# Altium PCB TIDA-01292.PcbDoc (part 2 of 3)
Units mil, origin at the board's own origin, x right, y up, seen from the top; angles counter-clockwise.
Board outline 6102.36 x 3543.31 mil, 2 copper layers (Top Layer, Bottom Layer), stack 64.8 mil thick; 118 components, 43 nets, 376 pads, 3910 vias.
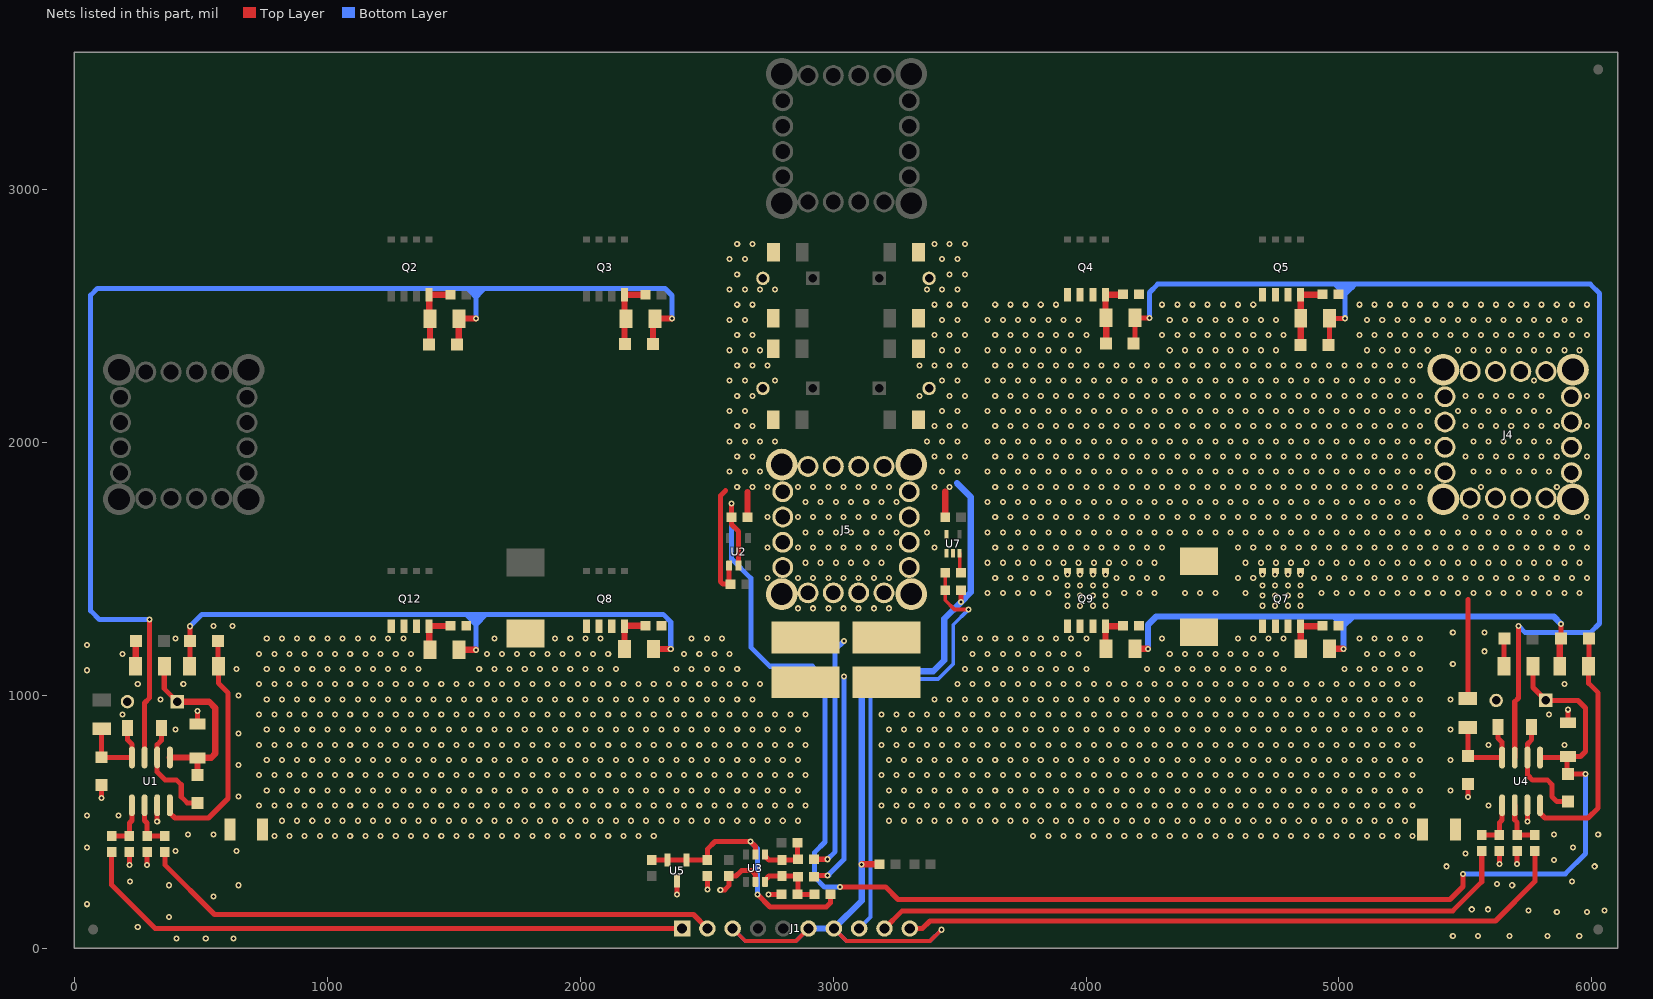
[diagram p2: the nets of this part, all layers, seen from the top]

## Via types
v1: diameter 24, hole 12, Top Layer to Bottom Layer, 3910 vias

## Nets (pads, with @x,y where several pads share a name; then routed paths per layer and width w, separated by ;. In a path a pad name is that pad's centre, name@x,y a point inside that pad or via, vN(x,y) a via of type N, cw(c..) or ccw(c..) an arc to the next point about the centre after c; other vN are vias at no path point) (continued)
"COMMON B": D11.1 J4.1 pad.1@5412.97,1776.37 pad.1@5412.97,2288.18 pad.1@5924.78,1776.37 pad.1@5924.78,2288.18 Q4.1 Q4.2 Q4.3 Q5.1 Q5.2 Q5.3 Q7.5 Q7.6 Q7.7 Q7.8 Q9.5 Q9.6 Q9.7 Q9.8 R27.2 R34.1 R35.1 | length 392.4
  Top Layer w20: R27.2@5510,987.6 5510,1380
  other v1: 3927,1355 3977,1355 4027,1355 4077,1355 4698,1355 4748,1355 4798,1355 4848,1355 3927,1395 3977,1395 4027,1395 4077,1395 4698,1395 4748,1395 4798,1395 4848,1395 3611.15,1405 3671.15,1405 3731.15,1405 3791.15,1405 3851.15,1405 4151.15,1405 4211.15,1405 4271.15,1405 4391.15,1405 4451.15,1405 4511.15,1405 4631.15,1405 4931.15,1405 4991.15,1405 5051.15,1405 5111.15,1405 5171.15,1405 5231.15,1405 5291.15,1405 5351.15,1405 5411.15,1405 5471.15,1405 5531.15,1405 5591.15,1405 5651.15,1405 5711.15,1405 5771.15,1405 5831.15,1405 5891.15,1405 5951.15,1405 3927,1435 3977,1435 4027,1435 4077,1435 4698,1435 4748,1435 4798,1435 4848,1435 3641.15,1465 3701.15,1465 3761.15,1465 3821.15,1465 3881.15,1465 4121.15,1465 4181.15,1465 4241.15,1465 4301.15,1465 4601.15,1465 4661.15,1465 4901.15,1465 4961.15,1465 5021.15,1465 5081.15,1465 5141.15,1465 5201.15,1465 5261.15,1465 5321.15,1465 5381.15,1465 5441.15,1465 5501.15,1465 5561.15,1465 5621.15,1465 5681.15,1465 5741.15,1465 5801.15,1465 5861.15,1465 5921.15,1465 5981.15,1465 3927,1479 3977,1479 4027,1479 4077,1479 4698,1479 4748,1479 4798,1479 4848,1479 3611.15,1525 3671.15,1525 3731.15,1525 3791.15,1525 3851.15,1525 3911.15,1525 3971.15,1525 4031.15,1525 4091.15,1525 4151.15,1525 4211.15,1525 4271.15,1525 4631.15,1525 4691.15,1525 4751.15,1525 4811.15,1525 4871.15,1525 4931.15,1525 4991.15,1525 5051.15,1525 5111.15,1525 5171.15,1525 5231.15,1525 5291.15,1525 5351.15,1525 5411.15,1525 5471.15,1525 5531.15,1525 5591.15,1525 5651.15,1525 5711.15,1525 5771.15,1525 5831.15,1525 5891.15,1525 5951.15,1525 3641.15,1585 3701.15,1585 3761.15,1585 3821.15,1585 3881.15,1585 3941.15,1585 4001.15,1585 4061.15,1585 4121.15,1585 4181.15,1585 4241.15,1585 4301.15,1585 4601.15,1585 4661.15,1585 4721.15,1585 4781.15,1585 4841.15,1585 4901.15,1585 4961.15,1585 5021.15,1585 5081.15,1585 5141.15,1585 5201.15,1585 5261.15,1585 5321.15,1585 5381.15,1585 5441.15,1585 5501.15,1585 5561.15,1585 5621.15,1585 5681.15,1585 5741.15,1585 5801.15,1585 5861.15,1585 5921.15,1585 5981.15,1585 3611.15,1645 3671.15,1645 3731.15,1645 3791.15,1645 3851.15,1645 3911.15,1645 3971.15,1645 4031.15,1645 4091.15,1645 4151.15,1645 4211.15,1645 4271.15,1645 4331.15,1645 4391.15,1645 4451.15,1645 4511.15,1645 4571.15,1645 4631.15,1645 4691.15,1645 4751.15,1645 4811.15,1645 4871.15,1645 4931.15,1645 4991.15,1645 5051.15,1645 5111.15,1645 5171.15,1645 5231.15,1645 5291.15,1645 5351.15,1645 5411.15,1645 5471.15,1645 5531.15,1645 5591.15,1645 5651.15,1645 5711.15,1645 5771.15,1645 5831.15,1645 5891.15,1645 5951.15,1645 3641.15,1705 3701.15,1705 3761.15,1705 3821.15,1705 3881.15,1705 3941.15,1705 4001.15,1705 4061.15,1705 4121.15,1705 4181.15,1705 4241.15,1705 4301.15,1705 4361.15,1705 4421.15,1705 4481.15,1705 4541.15,1705 4601.15,1705 4661.15,1705 4721.15,1705 4781.15,1705 4841.15,1705 4901.15,1705 4961.15,1705 5021.15,1705 5081.15,1705 5141.15,1705 5201.15,1705 5261.15,1705 5321.15,1705 5501.15,1705 5561.15,1705 5621.15,1705 5681.15,1705 5741.15,1705 5801.15,1705 5861.15,1705 5981.15,1705 3611.15,1765 3671.15,1765 3731.15,1765 3791.15,1765 3851.15,1765 3911.15,1765 3971.15,1765 4031.15,1765 4091.15,1765 4151.15,1765 4211.15,1765 4271.15,1765 4331.15,1765 4391.15,1765 4451.15,1765 4511.15,1765 4571.15,1765 4631.15,1765 4691.15,1765 4751.15,1765 4811.15,1765 4871.15,1765 4931.15,1765 4991.15,1765 5051.15,1765 5111.15,1765 5171.15,1765 5231.15,1765 5291.15,1765 3641.15,1825 3701.15,1825 3761.15,1825 3821.15,1825 3881.15,1825 3941.15,1825 4001.15,1825 4061.15,1825 4121.15,1825 4181.15,1825 4241.15,1825 4301.15,1825 4361.15,1825 4421.15,1825 4481.15,1825 4541.15,1825 4601.15,1825 4661.15,1825 4721.15,1825 4781.15,1825 4841.15,1825 4901.15,1825 4961.15,1825 5021.15,1825 5081.15,1825 5141.15,1825 5201.15,1825 5261.15,1825 5321.15,1825 5561.15,1825 5861.15,1825 3611.15,1885 3671.15,1885 3731.15,1885 3791.15,1885 3851.15,1885 3911.15,1885 3971.15,1885 4031.15,1885 4091.15,1885 4151.15,1885 4211.15,1885 4271.15,1885 4331.15,1885 4391.15,1885 4451.15,1885 4511.15,1885 4571.15,1885 4631.15,1885 4691.15,1885 4751.15,1885 4811.15,1885 4871.15,1885 4931.15,1885 4991.15,1885 5051.15,1885 5111.15,1885 5171.15,1885 5231.15,1885 5291.15,1885 5351.15,1885 5531.15,1885 5591.15,1885 5651.15,1885 5711.15,1885 5771.15,1885 5831.15,1885 3641.15,1945 3701.15,1945 3761.15,1945 3821.15,1945 3881.15,1945 3941.15,1945 4001.15,1945 4061.15,1945 4121.15,1945 4181.15,1945 4241.15,1945 4301.15,1945 4361.15,1945 4421.15,1945 4481.15,1945 4541.15,1945 4601.15,1945 4661.15,1945 4721.15,1945 4781.15,1945 4841.15,1945 4901.15,1945 4961.15,1945 5021.15,1945 5081.15,1945 5141.15,1945 5201.15,1945 5261.15,1945 5321.15,1945 5501.15,1945 5561.15,1945 5621.15,1945 5681.15,1945 5741.15,1945 5801.15,1945 5861.15,1945 5981.15,1945 3611.15,2005 3671.15,2005 3731.15,2005 3791.15,2005 3851.15,2005 3911.15,2005 3971.15,2005 4031.15,2005 4091.15,2005 4151.15,2005 4211.15,2005 4271.15,2005 4331.15,2005 4391.15,2005 4451.15,2005 4511.15,2005 4571.15,2005 4631.15,2005 4691.15,2005 4751.15,2005 4811.15,2005 4871.15,2005 4931.15,2005 4991.15,2005 5051.15,2005 5111.15,2005 5171.15,2005 5231.15,2005 5291.15,2005 5351.15,2005 5531.15,2005 5591.15,2005 5651.15,2005 5711.15,2005 5771.15,2005 5831.15,2005 3641.15,2065 3701.15,2065 3761.15,2065 3821.15,2065 3881.15,2065 3941.15,2065 4001.15,2065 4061.15,2065 4121.15,2065 4181.15,2065 4241.15,2065 4301.15,2065 4361.15,2065 4421.15,2065 4481.15,2065 4541.15,2065 4601.15,2065 4661.15,2065 4721.15,2065 4781.15,2065 4841.15,2065 4901.15,2065 4961.15,2065 5021.15,2065 5081.15,2065 5141.15,2065 5201.15,2065 5261.15,2065 5321.15,2065 5501.15,2065 5561.15,2065 5621.15,2065 5681.15,2065 5741.15,2065 5801.15,2065 5861.15,2065 5981.15,2065 3611.15,2125 3671.15,2125 3731.15,2125 3791.15,2125 3851.15,2125 3911.15,2125 3971.15,2125 4031.15,2125 4091.15,2125 4151.15,2125 4211.15,2125 4271.15,2125 4331.15,2125 4391.15,2125 4451.15,2125 4511.15,2125 4571.15,2125 4631.15,2125 4691.15,2125 4751.15,2125 4811.15,2125 4871.15,2125 4931.15,2125 4991.15,2125 5051.15,2125 5111.15,2125 5171.15,2125 5231.15,2125 5291.15,2125 5351.15,2125 5471.15,2125 5531.15,2125 5591.15,2125 5651.15,2125 5711.15,2125 5771.15,2125 5831.15,2125 3641.15,2185 3701.15,2185 3761.15,2185 3821.15,2185 3881.15,2185 3941.15,2185 4001.15,2185 4061.15,2185 4121.15,2185 4181.15,2185 4241.15,2185 4301.15,2185 4361.15,2185 4421.15,2185 4481.15,2185 4541.15,2185 4601.15,2185 4661.15,2185 4721.15,2185 4781.15,2185 4841.15,2185 4901.15,2185 4961.15,2185 5021.15,2185 5081.15,2185 5141.15,2185 5201.15,2185 5261.15,2185 5321.15,2185 5501.15,2185 5561.15,2185 5621.15,2185 5681.15,2185 5741.15,2185 5801.15,2185 5981.15,2185 3611.15,2245 3671.15,2245 3731.15,2245 3791.15,2245 3851.15,2245 3911.15,2245 3971.15,2245 4031.15,2245 4091.15,2245 4151.15,2245 4211.15,2245 4271.15,2245 4331.15,2245 4391.15,2245 4451.15,2245 4511.15,2245 4571.15,2245 4631.15,2245 4691.15,2245 4751.15,2245 4811.15,2245 4871.15,2245 4931.15,2245 4991.15,2245 5051.15,2245 5111.15,2245 5171.15,2245 5231.15,2245 5291.15,2245 5771.15,2245 3641.15,2305 3701.15,2305 3761.15,2305 3821.15,2305 3881.15,2305 3941.15,2305 4001.15,2305 4061.15,2305 4121.15,2305 4181.15,2305 4241.15,2305 4301.15,2305 4361.15,2305 4421.15,2305 4481.15,2305 4541.15,2305 4601.15,2305 4661.15,2305 4721.15,2305 4781.15,2305 4841.15,2305 4901.15,2305 4961.15,2305 5021.15,2305 5081.15,2305 5141.15,2305 5201.15,2305 5261.15,2305 5321.15,2305 3611.15,2365 3671.15,2365 3731.15,2365 3791.15,2365 3851.15,2365 3911.15,2365 3971.15,2365 4331.15,2365 4391.15,2365 4451.15,2365 4511.15,2365 4571.15,2365 4631.15,2365 4691.15,2365 4751.15,2365 5111.15,2365 5171.15,2365 5231.15,2365 5291.15,2365 5351.15,2365 5471.15,2365 5531.15,2365 5591.15,2365 5651.15,2365 5711.15,2365 5771.15,2365 5831.15,2365 5891.15,2365 5951.15,2365 3641.15,2425 3701.15,2425 3761.15,2425 3821.15,2425 3881.15,2425 3941.15,2425 4001.15,2425 4301.15,2425 4361.15,2425 4421.15,2425 4481.15,2425 4541.15,2425 4601.15,2425 4661.15,2425 4721.15,2425 4781.15,2425 5081.15,2425 5141.15,2425 5201.15,2425 5261.15,2425 5321.15,2425 5381.15,2425 5441.15,2425 5501.15,2425 5561.15,2425 5621.15,2425 5681.15,2425 5741.15,2425 5801.15,2425 5861.15,2425 5921.15,2425 5981.15,2425 3611.15,2485 3671.15,2485 3731.15,2485 3791.15,2485 3851.15,2485 3911.15,2485 3971.15,2485 4331.15,2485 4391.15,2485 4451.15,2485 4511.15,2485 4571.15,2485 4631.15,2485 4691.15,2485 4751.15,2485 5111.15,2485 5171.15,2485 5231.15,2485 5291.15,2485 5351.15,2485 5411.15,2485 5471.15,2485 5531.15,2485 5591.15,2485 5651.15,2485 5711.15,2485 5771.15,2485 5831.15,2485 5891.15,2485 5951.15,2485 3641.15,2545 3701.15,2545 3761.15,2545 3821.15,2545 3881.15,2545 4301.15,2545 4361.15,2545 4421.15,2545 4481.15,2545 4541.15,2545 4601.15,2545 4661.15,2545 5081.15,2545 5141.15,2545 5201.15,2545 5261.15,2545 5321.15,2545 5381.15,2545 5441.15,2545 5501.15,2545 5561.15,2545 5621.15,2545 5681.15,2545 5741.15,2545 5801.15,2545 5861.15,2545 5921.15,2545 5981.15,2545
GHIA: D3.1 D4.1 R7.1 R8.1 U1.3 | length 5020
  Top Layer w20: U1.3@278.15,755.34 278.15,970.85 298.15,990.85 v1(298.15,1300.85)
  Top Layer w25: D3.1@1513.5,2388.4 1520.47,2395.37 R7.1@1520.47,2490.26 v1(1588.39,2490.26) ; D4.1@2288.5,2389.3 R8.1@2288.5,2483.29 ; R8.1@2295.47,2490.26 v1(2363.39,2490.26)
  Bottom Layer w20: v1(298.15,1300.85) 99.15,1300.85 65,1335 65,2582.43 92.4,2609.82 1554.24,2609.82 ; v1(1588.39,2490.26) 1588.39,2575.68 ; 1622.56,2609.85 1609.46,2596.75 ; v1(2363.39,2490.26) 2363.39,2581.61 2335.18,2609.82 1636.36,2609.82 1554.24,2609.82 ; 1554.24,2609.82 1567.31,2596.75 ; 1567.31,2596.75 1588.39,2575.68 ; 1567.31,2596.75 1609.46,2596.75 ; 1588.39,2575.68 1609.46,2596.75
GHIB: D5.1 D6.1 R10.1 R11.1 U4.3 | length 4715.2
  Top Layer w20: D5.1@4188.42,2391.09 4193.66,2396.33 R10.1@4193.66,2492.73 v1(4250.84,2492.73) ; D6.1@4958.42,2386.09 4963.08,2390.75 R11.1@4963.08,2491.42 v1(5024.33,2491.42) ; U4.3@5695,755 5695,975.51 5710,990.51 v1@5710,1273.28
  Bottom Layer w20: v1(4250.84,2492.73) 4250.84,2593.49 4283.61,2626.26 4984.67,2626.26 ; 4999.45,2611.49 5049.2,2611.49 5063.98,2626.26 ; v1(5024.33,2491.42) 5024.33,2586.61 ; 5024.33,2611.49 5024.33,2586.61 ; v1(5710,1275) 5735,1250 5995,1250 6030,1285 6030,2590 5993.74,2626.26 5063.98,2626.26 ; 4984.67,2626.26 5024.33,2586.61 ; 4984.67,2626.26 5063.98,2626.26 ; 5024.33,2586.61 5063.98,2626.26
GLIA: D15.1 R16.1 U1.8 | length 940
  Top Layer w20: U1.8@378.15,566.36 378.15,535.85 398.15,515.85 530.85,515.85 608.15,593.15 608.15,1010.85 570.24,1048.76 R16.1@570.24,1115.6 568.27,1117.57 D15.1@568.27,1215.85
GLIB: D12.1 R22.1 U4.8 | length 966.8
  Top Layer w20: U4.8@5795,566.02 5795,535.51 5815,515.51 5985,515.51 6025,555.51 6025,1010.51 5987.09,1048.43 R22.1@5987.09,1115.26 5987.84,1116.01 D12.1@5987.84,1220.92
GND: C1.2 C2.2 C3.2 C5.2 C6.2 C7.2 C8.2 C11.2 C12.2 C13.2 C14.2 C15.2 C18.2 C19.2 C20.2 C21.2 CB1.2 CB2.2 CB3.2 CB4.2 CB5.2 CB6.2 CB7.2 CB8.2 CB9.2 CB10.2 CB11.2 CB12.2 D9.2 D18.2 J1.3 J1.6 J1.7 J5.1 pad.1@2797.2,1401.03 pad.1@2797.2,1912.84 pad.1@3309.01,1401.03 pad.1@3309.01,1912.84 R2.1 R3.1 R4.1 R15.1 R18.2 U1.7 U2.1 U3.2 U4.7 U5.3 U7.1 U7.2 U7.5 | length 6646.6
  Top Layer w15: J1.3@2603.15,79 2653.15,29 2853.15,29 J1.6@2903.15,79 ; J1.7@3003.15,79 3053.15,29 3383.15,29 v1(3428.15,74)
  Top Layer w20: v1(108.15,594.24) D9.2@108.15,645.73 ; v1(218.15,329.35) C1.2@218.15,380.85 ; v1(288.15,329.35) C2.2@288.15,380.85 ; v1(328.15,502.31) U1.7@328.15,566.36 ; C11.2@487.64,887.78 v1(487.64,939.28) ; v1(2383.15,214.16) U5.3@2383.15,266.4 ; C12.2@2497.09,280.18 C12.2@2503.15,286.24 v1(2503.15,234) ; v1(2554.15,232) 2572,232 2588.15,248.15 C15.2@2588.15,286.24 2616.65,286.24 2638.15,307.74 2678.15,307.74 2693.15,292.74 U3.2@2693.15,263.61 ; 2575,1810 2555,1790 2555,1450 2564.15,1440.85 C8.2@2595.16,1440.85 2589.25,1446.76 U2.1@2589.25,1513.79 ; v1(2744.41,214) R18.2@2796.65,214 ; R2.1@2874.57,1210.85 2849.57,1235.85 2843.15,1229.43 R2.1@2891.73,1180.85 ; R4.1@2924.65,352.74 v1(2978.15,352.74) ; v1(3506.5,1370) C19.2@3506.5,1415.78 ; v1(5510,598.9) D18.2@5510,650.39 ; v1(5634.61,334.02) C3.2@5634.61,385.51 ; v1(5704.61,334.02) C5.2@5704.61,385.51 ; v1(5745,501.97) U4.7@5745,566.02 ; C14.2@5905.36,892.44 v1(5905.36,943.94)
  Top Layer w25: C7.2@2661.5,1705 2661.5,1803.5 ; v1(3113.15,332.74) R15.1@3183.15,332.74 ; C18.2@3443.5,1705 3443.5,1806.5
  Bottom Layer w15: J1.3@2603.15,79 2653.15,29 2853.15,29 J1.6@2903.15,79 ; J1.7@3003.15,79 3053.15,29 3383.15,29 v1(3428.15,74)
  Bottom Layer w20: v1(2978.15,352.74) 3008.15,382.74 3008.15,1180.85 v1(3043.15,1215.85)
  Bottom Layer w25: J1.6@2903.15,79 J1.7@3003.15,79 3113.15,189 v1(3113.15,332.74) 3113.15,418 3113.15,502.15 3113.15,1040.85 3168.15,1095.85 3395.85,1095.85 3440,1140 3440,1303.5 v1(3506.5,1370) 3545,1408.5 3545,1785 3490,1840
  other v1: 405,40 520,40 630,40 5450,50 5550,50 5675,50 5825,50 5950,50 251.15,85 375,125 5861.15,145 5981.15,145 5750,150 6050,150 5525,155 5590,155 50,175 551.15,205 375,250 650,250 5685,250 5625,255 221.15,265 5921.15,265 5425,325 6011.15,325 5850,350 5500,375 401.15,385 641.15,385 50,400 5925,400 450,450 550,450 5850,450 6025,450 50,525 175,525 5591.15,565 650,600 5441.15,625 650,725 5441.15,745 5591.15,805 5891.15,805 650,850 401.15,865 5441.15,865 191.15,925 5831.15,925 341.15,985 5441.15,985 650,1000 251.15,1045 431.15,1045 5891.15,1045 50,1100 641.15,1105 5450,1125 191.15,1165 5575,1175 50,1200 401.15,1225 5450,1250 5575,1250 550,1275 625,1275 2861.15,1345 2921.15,1345 2981.15,1345 3041.15,1345 3101.15,1345 3161.15,1345 3221.15,1345 2741.15,1465 2861.15,1465 2921.15,1465 2981.15,1465 3041.15,1465 3101.15,1465 3161.15,1465 3221.15,1465 2891.15,1525 2951.15,1525 3011.15,1525 3071.15,1525 3131.15,1525 3191.15,1525 2741.15,1585 2861.15,1585 2921.15,1585 2981.15,1585 3041.15,1585 3101.15,1585 3161.15,1585 3221.15,1585 3401.15,1585 2891.15,1645 2951.15,1645 3011.15,1645 3071.15,1645 3131.15,1645 3191.15,1645 3251.15,1645 3371.15,1645 2741.15,1705 2861.15,1705 2921.15,1705 2981.15,1705 3041.15,1705 3101.15,1705 3161.15,1705 3221.15,1705 2891.15,1765 2951.15,1765 3011.15,1765 3071.15,1765 3131.15,1765 3191.15,1765 3251.15,1765 2621.15,1825 2681.15,1825 2741.15,1825 2861.15,1825 2921.15,1825 2981.15,1825 3041.15,1825 3101.15,1825 3161.15,1825 3221.15,1825 3401.15,1825 3461.15,1825 2591.15,1885 2651.15,1885 2711.15,1885 3431.15,1885 3491.15,1885 2621.15,1945 2681.15,1945 3401.15,1945 3461.15,1945 3521.15,1945 2591.15,2005 2651.15,2005 2711.15,2005 2771.15,2005 3371.15,2005 3431.15,2005 3491.15,2005 2621.15,2065 2681.15,2065 3401.15,2065 3461.15,2065 3521.15,2065 2591.15,2125 2651.15,2125 3431.15,2125 3491.15,2125 2621.15,2185 2681.15,2185 3341.15,2185 3461.15,2185 3521.15,2185 2591.15,2245 2651.15,2245 2771.15,2245 3431.15,2245 3491.15,2245 2621.15,2305 2681.15,2305 2741.15,2305 3341.15,2305 3401.15,2305 3461.15,2305 3521.15,2305 2591.15,2365 2651.15,2365 2711.15,2365 3431.15,2365 3491.15,2365 2621.15,2425 2681.15,2425 3401.15,2425 3461.15,2425 3521.15,2425 2591.15,2485 2651.15,2485 3431.15,2485 3491.15,2485 2621.15,2545 2681.15,2545 3401.15,2545 3461.15,2545 3521.15,2545 2591.15,2605 2651.15,2605 2711.15,2605 2771.15,2605 3371.15,2605 3431.15,2605 3491.15,2605 2621.15,2665 3461.15,2665 3521.15,2665 2591.15,2725 2651.15,2725 3431.15,2725 3491.15,2725 2621.15,2785 2681.15,2785 3401.15,2785 3461.15,2785 3521.15,2785
NetC4_1: C4.1 D8.1 U1.2 | length 417.8
  Top Layer w20: C4.1@345.08,870.85 345.08,822.78 328.15,805.85 U1.2@328.15,755.34 328.15,697.78 359.16,666.77 403.87,666.77 423.15,647.5 423.15,599.33 446.74,575.73 D8.1@487.13,575.73
NetC4_2: C4.2 D9.1 R26.1 U1.4 | length 355.6
  Top Layer w20: R26.1@108.15,868.76 D9.1@108.15,755.97 108.78,755.34 U1.4@228.15,755.34 228.15,806.98 211.22,823.91 C4.2@211.22,870.85
NetC6_1: C6.1 C11.1 D8.2 R28.2 U1.1 | length 757.5
  Top Layer w20: R28.2@356.07,1115.6 356.07,1027.19 C6.1@407.41,975.85
  Top Layer w25: U1.1@378.15,755.34 486.22,755.34 487.13,754.43 D8.2@487.13,685.97 ; C6.1@407.41,975.85 533.15,975.85 558.15,950.85 558.15,770.85 541.22,753.92 C11.1@487.64,753.92
NetC9_1: C9.1 R1.2 R18.1 R21.2 U3.3 | length 283.8
  Top Layer w20: U3.3@2730.55,263.61 2730.55,270.14 2746.65,286.24 C9.1@2798.15,286.24 2858.15,286.24 R1.2@2861.65,282.74 2861.65,216.01 R18.1@2859.65,214 ; R18.1@2858.15,214 R18.1@2859.65,214 ; R21.2@2926.65,214 R18.1@2859.65,214
NetC9_2: C9.2 R4.2 R20.2 U3.4 | length 211.6
  Top Layer w20: U3.4@2730.55,371.87 2730.55,365.34 2746.65,349.24 C9.2@2798.15,349.24 2858.15,349.24 R4.2@2861.65,352.74 2859.65,354.75 R20.2@2859.65,417.74
NetC10_1: C10.1 D17.1 U4.2 | length 429.7
  Top Layer w20: C10.1@5761.93,876.46 5761.93,825.44 5745,808.51 U4.2@5745,755 5745,685.51 5765,665.51 5825,665.51 5841.81,648.7 5841.81,600.51 5861.93,580.39 D17.1@5905,580.39
NetC10_2: C10.2 D18.1 R27.1 U4.4 | length 378.6
  Top Layer w20: R27.1@5510,873.43 D18.1@5510,760.63 5515.63,755 U4.4@5645,755 5645,815.51 5628.07,832.44 C10.2@5628.07,876.46
NetC12_1: C12.1 R5.1 R21.1 U3.5 U5.1 U5.2 | length 1075.7
  Top Layer w20: R5.1@2283.15,349.24 2283.31,349.08 U5.2@2345.75,349.08 U5.1@2420.55,349.08 2420.71,349.24 C12.1@2503.15,349.24 2503.15,392.74 2533.41,423 v1(2672.89,423) 2693.15,402.74 U3.5@2693.15,371.87 ; v1(2701.15,214) 2751.15,164 2973.15,164 2989.65,180.5 R21.1@2989.65,214
  Bottom Layer w20: v1(2672.89,423) 2701.15,394.74 v1(2701.15,214)
NetC20_1: C20.1 C21.1 D7.2 D11.2 Q7.1 Q7.2 Q7.3 Q8.1 Q8.2 Q8.3 Q9.1 Q9.2 Q9.3 Q12.1 Q12.2 Q12.3 R1.1 R2.2 R3.2 R37.1 R38.1 R40.1 R41.1 | length 979.7
  Top Layer w20: R2.2@2843.15,1052.27 2891.73,1100.85 R2.2@2916.73,1075.85 ; R1.1@2924.65,282.74 2929.65,287.74 v1(2978.15,287.74)
  Bottom Layer w20: v1@2983.15,287.74 v1(2978.15,287.74) 3043.15,352.74 v1(3043.15,1075.85)
  other v1: 791.15,445 851.15,445 911.15,445 971.15,445 1031.15,445 1091.15,445 1151.15,445 1211.15,445 1271.15,445 1331.15,445 1391.15,445 1451.15,445 1511.15,445 1571.15,445 1631.15,445 1691.15,445 1751.15,445 1811.15,445 1871.15,445 1931.15,445 1991.15,445 2051.15,445 2111.15,445 2171.15,445 2231.15,445 2291.15,445 3791.15,445 3851.15,445 3911.15,445 3971.15,445 4031.15,445 4091.15,445 4151.15,445 4211.15,445 4271.15,445 4331.15,445 4391.15,445 4451.15,445 4511.15,445 4571.15,445 4631.15,445 4691.15,445 4751.15,445 4811.15,445 4871.15,445 4931.15,445 4991.15,445 5051.15,445 5111.15,445 5171.15,445 5231.15,445 5291.15,445 821.15,505 881.15,505 941.15,505 1001.15,505 1061.15,505 1121.15,505 1181.15,505 1241.15,505 1301.15,505 1361.15,505 1421.15,505 1481.15,505 1541.15,505 1601.15,505 1661.15,505 1721.15,505 1781.15,505 1841.15,505 1901.15,505 1961.15,505 2021.15,505 2081.15,505 2141.15,505 2201.15,505 2261.15,505 2321.15,505 2381.15,505 2441.15,505 2501.15,505 2561.15,505 2621.15,505 2681.15,505 2741.15,505 2801.15,505 2861.15,505 3221.15,505 3281.15,505 3341.15,505 3401.15,505 3461.15,505 3521.15,505 3581.15,505 3641.15,505 3701.15,505 3761.15,505 3821.15,505 3881.15,505 3941.15,505 4001.15,505 4061.15,505 4121.15,505 4181.15,505 4241.15,505 4301.15,505 4361.15,505 4421.15,505 4481.15,505 4541.15,505 4601.15,505 4661.15,505 4721.15,505 4781.15,505 4841.15,505 4901.15,505 4961.15,505 5021.15,505 5081.15,505 5141.15,505 5201.15,505 5261.15,505 731.15,565 791.15,565 851.15,565 911.15,565 971.15,565 1031.15,565 1091.15,565 1151.15,565 1211.15,565 1271.15,565 1331.15,565 1391.15,565 1451.15,565 1511.15,565 1571.15,565 1631.15,565 1691.15,565 1751.15,565 1811.15,565 1871.15,565 1931.15,565 1991.15,565 2051.15,565 2111.15,565 2171.15,565 2231.15,565 2291.15,565 2351.15,565 2411.15,565 2471.15,565 2531.15,565 2591.15,565 2651.15,565 2711.15,565 2771.15,565 2831.15,565 2891.15,565 3191.15,565 3251.15,565 3311.15,565 3371.15,565 3431.15,565 3491.15,565 3551.15,565 3611.15,565 3671.15,565 3731.15,565 3791.15,565 3851.15,565 3911.15,565 3971.15,565 4031.15,565 4091.15,565 4151.15,565 4211.15,565 4271.15,565 4331.15,565 4391.15,565 4451.15,565 4511.15,565 4571.15,565 4631.15,565 4691.15,565 4751.15,565 4811.15,565 4871.15,565 4931.15,565 4991.15,565 5051.15,565 5111.15,565 5171.15,565 5231.15,565 5291.15,565 761.15,625 821.15,625 881.15,625 941.15,625 1001.15,625 1061.15,625 1121.15,625 1181.15,625 1241.15,625 1301.15,625 1361.15,625 1421.15,625 1481.15,625 1541.15,625 1601.15,625 1661.15,625 1721.15,625 1781.15,625 1841.15,625 1901.15,625 1961.15,625 2021.15,625 2081.15,625 2141.15,625 2201.15,625 2261.15,625 2321.15,625 2381.15,625 2441.15,625 2501.15,625 2561.15,625 2621.15,625 2681.15,625 2741.15,625 2801.15,625 2861.15,625 3221.15,625 3281.15,625 3341.15,625 3401.15,625 3461.15,625 3521.15,625 3581.15,625 3641.15,625 3701.15,625 3761.15,625 3821.15,625 3881.15,625 3941.15,625 4001.15,625 4061.15,625 4121.15,625 4181.15,625 4241.15,625 4301.15,625 4361.15,625 4421.15,625 4481.15,625 4541.15,625 4601.15,625 4661.15,625 4721.15,625 4781.15,625 4841.15,625 4901.15,625 4961.15,625 5021.15,625 5081.15,625 5141.15,625 5201.15,625 5261.15,625 5321.15,625 731.15,685 791.15,685 851.15,685 911.15,685 971.15,685 1031.15,685 1091.15,685 1151.15,685 1211.15,685 1271.15,685 1331.15,685 1391.15,685 1451.15,685 1511.15,685 1571.15,685 1631.15,685 1691.15,685 1751.15,685 1811.15,685 1871.15,685 1931.15,685 1991.15,685 2051.15,685 2111.15,685 2171.15,685 2231.15,685 2291.15,685 2351.15,685 2411.15,685 2471.15,685 2531.15,685 2591.15,685 2651.15,685 2711.15,685 2771.15,685 2831.15,685 2891.15,685 3191.15,685 3251.15,685 3311.15,685 3371.15,685 3431.15,685 3491.15,685 3551.15,685 3611.15,685 3671.15,685 3731.15,685 3791.15,685 3851.15,685 3911.15,685 3971.15,685 4031.15,685 4091.15,685 4151.15,685 4211.15,685 4271.15,685 4331.15,685 4391.15,685 4451.15,685 4511.15,685 4571.15,685 4631.15,685 4691.15,685 4751.15,685 4811.15,685 4871.15,685 4931.15,685 4991.15,685 5051.15,685 5111.15,685 5171.15,685 5231.15,685 5291.15,685 761.15,745 821.15,745 881.15,745 941.15,745 1001.15,745 1061.15,745 1121.15,745 1181.15,745 1241.15,745 1301.15,745 1361.15,745 1421.15,745 1481.15,745 1541.15,745 1601.15,745 1661.15,745 1721.15,745 1781.15,745 1841.15,745 1901.15,745 1961.15,745 2021.15,745 2081.15,745 2141.15,745 2201.15,745 2261.15,745 2321.15,745 2381.15,745 2441.15,745 2501.15,745 2561.15,745 2621.15,745 2681.15,745 2741.15,745 2801.15,745 2861.15,745 3221.15,745 3281.15,745 3341.15,745 3401.15,745 3461.15,745 3521.15,745 3581.15,745 3641.15,745 3701.15,745 3761.15,745 3821.15,745 3881.15,745 3941.15,745 4001.15,745 4061.15,745 4121.15,745 4181.15,745 4241.15,745 4301.15,745 4361.15,745 4421.15,745 4481.15,745 4541.15,745 4601.15,745 4661.15,745 4721.15,745 4781.15,745 4841.15,745 4901.15,745 4961.15,745 5021.15,745 5081.15,745 5141.15,745 5201.15,745 5261.15,745 5321.15,745 731.15,805 791.15,805 851.15,805 911.15,805 971.15,805 1031.15,805 1091.15,805 1151.15,805 1211.15,805 1271.15,805 1331.15,805 1391.15,805 1451.15,805 1511.15,805 1571.15,805 1631.15,805 1691.15,805 1751.15,805 1811.15,805 1871.15,805 1931.15,805 1991.15,805 2051.15,805 2111.15,805 2171.15,805 2231.15,805 2291.15,805 2351.15,805 2411.15,805 2471.15,805 2531.15,805 2591.15,805 2651.15,805 2711.15,805 2771.15,805 2831.15,805 2891.15,805 3191.15,805 3251.15,805 3311.15,805 3371.15,805 3431.15,805 3491.15,805 3551.15,805 3611.15,805 3671.15,805 3731.15,805 3791.15,805 3851.15,805 3911.15,805 3971.15,805 4031.15,805 4091.15,805 4151.15,805 4211.15,805 4271.15,805 4331.15,805 4391.15,805 4451.15,805 4511.15,805 4571.15,805 4631.15,805 4691.15,805 4751.15,805 4811.15,805 4871.15,805 4931.15,805 4991.15,805 5051.15,805 5111.15,805 5171.15,805 5231.15,805 5291.15,805 761.15,865 821.15,865 881.15,865 941.15,865 1001.15,865 1061.15,865 1121.15,865 1181.15,865 1241.15,865 1301.15,865 1361.15,865 1421.15,865 1481.15,865 1541.15,865 1601.15,865 1661.15,865 1721.15,865 1781.15,865 1841.15,865 1901.15,865 1961.15,865 2021.15,865 2081.15,865 2141.15,865 2201.15,865 2261.15,865 2321.15,865 2381.15,865 2441.15,865 2501.15,865 2561.15,865 2621.15,865 2681.15,865 2741.15,865 2801.15,865 2861.15,865 3221.15,865 3281.15,865 3341.15,865 3401.15,865 3461.15,865 3521.15,865 3581.15,865 3641.15,865 3701.15,865 3761.15,865 3821.15,865 3881.15,865 3941.15,865 4001.15,865 4061.15,865 4121.15,865 4181.15,865 4241.15,865 4301.15,865 4361.15,865 4421.15,865 4481.15,865 4541.15,865 4601.15,865 4661.15,865 4721.15,865 4781.15,865 4841.15,865 4901.15,865 4961.15,865 5021.15,865 5081.15,865 5141.15,865 5201.15,865 5261.15,865 5321.15,865 731.15,925 791.15,925 851.15,925 911.15,925 971.15,925 1031.15,925 1091.15,925 1151.15,925 1211.15,925 1271.15,925 1331.15,925 1391.15,925 1451.15,925 1511.15,925 1571.15,925 1631.15,925 1691.15,925 1751.15,925 1811.15,925 1871.15,925 1931.15,925 1991.15,925 2051.15,925 2111.15,925 2171.15,925 2231.15,925 2291.15,925 2351.15,925 2411.15,925 2471.15,925 2531.15,925 2591.15,925 2651.15,925 2711.15,925 2771.15,925 2831.15,925 2891.15,925 3191.15,925 3251.15,925 3311.15,925 3371.15,925 3431.15,925 3491.15,925 3551.15,925 3611.15,925 3671.15,925 3731.15,925 3791.15,925 3851.15,925 3911.15,925 3971.15,925 4031.15,925 4091.15,925 4151.15,925 4211.15,925 4271.15,925 4331.15,925 4391.15,925 4451.15,925 4511.15,925 4571.15,925 4631.15,925 4691.15,925 4751.15,925 4811.15,925 4871.15,925 4931.15,925 4991.15,925 5051.15,925 5111.15,925 5171.15,925 5231.15,925 5291.15,925 761.15,985 821.15,985 881.15,985 941.15,985 1001.15,985 1061.15,985 1121.15,985 1181.15,985 1241.15,985 1301.15,985 1361.15,985 1421.15,985 1481.15,985 1541.15,985 1601.15,985 1661.15,985 1721.15,985 1781.15,985 1841.15,985 1901.15,985 1961.15,985 2021.15,985 2081.15,985 2141.15,985 2201.15,985 2261.15,985 2321.15,985 2381.15,985 2441.15,985 2501.15,985 2561.15,985 2621.15,985 2681.15,985 3401.15,985 3461.15,985 3521.15,985 3581.15,985 3641.15,985 3701.15,985 3761.15,985 3821.15,985 3881.15,985 3941.15,985 4001.15,985 4061.15,985 4121.15,985 4181.15,985 4241.15,985 4301.15,985 4361.15,985 4421.15,985 4481.15,985 4541.15,985 4601.15,985 4661.15,985 4721.15,985 4781.15,985 4841.15,985 4901.15,985 4961.15,985 5021.15,985 5081.15,985 5141.15,985 5201.15,985 5261.15,985 5321.15,985 731.15,1045 791.15,1045 851.15,1045 911.15,1045 971.15,1045 1031.15,1045 1091.15,1045 1151.15,1045 1211.15,1045 1271.15,1045 1331.15,1045 1391.15,1045 1451.15,1045 1511.15,1045 1571.15,1045 1631.15,1045 1691.15,1045 1751.15,1045 1811.15,1045 1871.15,1045 1931.15,1045 1991.15,1045 2051.15,1045 2111.15,1045 2171.15,1045 2231.15,1045 2291.15,1045 2351.15,1045 2411.15,1045 2471.15,1045 2531.15,1045 2591.15,1045 2651.15,1045 2711.15,1045 3491.15,1045 3551.15,1045 3611.15,1045 3671.15,1045 3731.15,1045 3791.15,1045 3851.15,1045 3911.15,1045 3971.15,1045 4031.15,1045 4091.15,1045 4151.15,1045 4211.15,1045 4271.15,1045 4331.15,1045 4391.15,1045 4451.15,1045 4511.15,1045 4571.15,1045 4631.15,1045 4691.15,1045 4751.15,1045 4811.15,1045 4871.15,1045 4931.15,1045 4991.15,1045 5051.15,1045 5111.15,1045 5171.15,1045 5231.15,1045 5291.15,1045 761.15,1105 821.15,1105 881.15,1105 941.15,1105 1001.15,1105 1061.15,1105 1121.15,1105 1181.15,1105 1241.15,1105 1301.15,1105 1361.15,1105 1601.15,1105 1661.15,1105 1721.15,1105 1781.15,1105 1841.15,1105 1901.15,1105 1961.15,1105 2021.15,1105 2081.15,1105 2141.15,1105 2381.15,1105 2441.15,1105 2501.15,1105 2561.15,1105 2621.15,1105 3521.15,1105 3581.15,1105 3641.15,1105 3701.15,1105 3761.15,1105 3821.15,1105 3881.15,1105 3941.15,1105 4001.15,1105 4241.15,1105 4301.15,1105 4361.15,1105 4421.15,1105 4481.15,1105 4541.15,1105 4601.15,1105 4661.15,1105 4721.15,1105 4781.15,1105 5021.15,1105 5081.15,1105 5141.15,1105 5201.15,1105 5261.15,1105 5321.15,1105 731.15,1165 791.15,1165 851.15,1165 911.15,1165 971.15,1165 1031.15,1165 1091.15,1165 1151.15,1165 1211.15,1165 1271.15,1165 1331.15,1165 1631.15,1165 1691.15,1165 1751.15,1165 1811.15,1165 1871.15,1165 1931.15,1165 1991.15,1165 2051.15,1165 2111.15,1165 2411.15,1165 2471.15,1165 2531.15,1165 2591.15,1165 3551.15,1165 3611.15,1165 3671.15,1165 3731.15,1165 3791.15,1165 3851.15,1165 3911.15,1165 3971.15,1165 4331.15,1165 4391.15,1165 4451.15,1165 4511.15,1165 4571.15,1165 4631.15,1165 4691.15,1165 4751.15,1165 5111.15,1165 5171.15,1165 5231.15,1165 5291.15,1165 761.15,1225 821.15,1225 881.15,1225 941.15,1225 1001.15,1225 1061.15,1225 1121.15,1225 1181.15,1225 1241.15,1225 1301.15,1225 1661.15,1225 1901.15,1225 1961.15,1225 2021.15,1225 2081.15,1225 2441.15,1225 2501.15,1225 2561.15,1225 3521.15,1225 3581.15,1225 3641.15,1225 3701.15,1225 3761.15,1225 3821.15,1225 3881.15,1225 3941.15,1225 4001.15,1225 4301.15,1225 4601.15,1225 4661.15,1225 4721.15,1225 4781.15,1225 5081.15,1225 5141.15,1225 5201.15,1225 5261.15,1225 5321.15,1225
NetD1_1: D1.1 R28.1 | length 105.8
  Top Layer w25: R28.1@241.9,1110.6 243.86,1112.57 D1.1@243.86,1215.6
NetD2_1: D2.1 R29.1 | length 111.1
  Top Layer w20: R29.1@5652.91,1115.26 5652.91,1223.54 D2.1@5654.88,1225.51
NetD3_2: D3.2 Q2.4 R7.2 R31.2 | length 267.1
  Top Layer w25: D3.2@1403.27,2388.4 1406.3,2391.44 R7.2@1406.3,2490.26 ; R7.2@1403.38,2493.17 Q2.4@1403.38,2584.03 R31.2@1476.56,2584.03
NetD4_2: D4.2 Q3.4 R8.2 R32.2 | length 270
  Top Layer w25: D4.2@2175.17,2392.39 Q3.4@2175.17,2584.03 ; Q3.4@2179.55,2584.69 R32.2@2257.89,2584.69
NetD5_2: D5.2 Q4.4 R10.2 R34.2 | length 265.7
  Top Layer w25: D5.2@4078.18,2391.09 4079.49,2392.4 R10.2@4079.49,2492.73 4076.83,2495.4 Q4.4@4076.83,2584.44 4145.16,2584.44 R34.2@4146.8,2586.09
NetD6_2: D6.2 Q5.4 R11.2 R35.2 | length 286.2
  Top Layer w25: D6.2@4848.18,2386.09 4848.91,2386.81 R11.2@4848.91,2491.42 4848.62,2491.72 Q5.4@4848.62,2584.44 4934.11,2584.44 R35.2@4935.5,2585.83
NetD12_2: D12.2 R22.2 R23.1 R25.1 | length 2258.8
  Top Layer w20: D12.2@5877.6,1225.51 v1(5877.6,1283.51)
  Top Layer w25: R23.1@4193.66,1184.38 v1(4245.04,1184.38) ; R25.1@4963.08,1184.38 v1(5017.68,1184.38) ; R22.2@5872.91,1115.26 5872.91,1216.23 D12.2@5877.6,1220.92
  Bottom Layer w25: v1(4245.04,1184.38) 4245.04,1280.1 4277.2,1312.26 4981.68,1312.26 ; 4997.68,1296.26 5037.68,1296.26 ; v1(5017.68,1184.38) 5017.68,1276.26 ; v1(5877.6,1283.51) 5848.85,1312.26 5053.68,1312.26 ; 4981.68,1312.26 5017.68,1276.26 ; 4981.68,1312.26 5053.68,1312.26 ; 5017.68,1276.26 5053.68,1312.26
NetD15_2: D15.2 R16.2 R17.1 R19.1 | length 2641.2
  Top Layer w20: R16.2@456.06,1115.6 458.03,1117.57 D15.2@458.03,1215.85 v1(458.03,1273.85)
  Top Layer w25: R17.1@1520.47,1180.68 v1(1588.39,1180.68) ; R19.1@2290.47,1183.97 v1(2358.39,1183.97)
  Bottom Layer w20: v1(458.03,1273.85) 505.03,1320.85 1547.38,1320.85 ; 1558.39,1309.85 1618.39,1309.85 ; 1572.39,1295.85 1604.39,1295.85 ; v1(1588.39,1180.68) 1588.39,1279.85 ; v1(2358.39,1183.97) 2358.39,1290.85 2328.39,1320.85 1629.39,1320.85 ; 1547.38,1320.85 1588.39,1279.85 ; 1547.38,1320.85 1629.39,1320.85 ; 1588.39,1279.85 1629.39,1320.85
NetQ7_4: Q7.4 R25.2 R41.2 | length 177.7
  Top Layer w25: R25.2@4848.91,1184.38 4848.62,1184.67 Q7.4@4848.62,1274.3 4933.72,1274.3 R41.2@4935.5,1276.09
NetQ8_4: Q8.4 R19.2 R38.2 | length 170.6
  Top Layer w25: Q8.4@2173.56,1275.68 R38.2@2257.89,1275.68 ; R19.2@2175.17,1187.64 Q8.4@2175.17,1273.89
NetQ9_4: Q9.4 R23.2 R40.2 | length 162.1
  Top Layer w25: R23.2@4078.3,1183.53 4076.83,1185 Q9.4@4076.83,1274.3 4145.02,1274.3 R40.2@4146.8,1276.09
NetQ12_4: Q12.4 R17.2 R37.2 | length 176
  Top Layer w25: R17.2@1404.21,1181.67 1404.21,1275.03 R37.2@1486.89,1275.03
NetR43_1: R43.1 U7.3 | length 80
  Top Layer w15: U7.3@3500.59,1562.6 3500.59,1490.91 R43.1@3506.5,1485
PWM_HI_AF: C1.1 R6.2 U1.5 | length 196.7
  Top Layer w20: R6.2@148.15,443.84 C1.1@218.15,443.84 218.15,495.85 228.15,505.85 U1.5@228.15,566.36
PWM_HI_BF: C3.1 R13.2 U4.5 | length 191.8
  Top Layer w20: R13.2@5564.61,448.5 C3.1@5634.61,448.5 5634.61,497.12 5645,507.51 U4.5@5645,566.02
PWM_HIA: J1.1 R6.1 | length 2456.2
  Top Layer w20: R6.1@148.15,380.85 148.15,250.85 320,79 J1.1@2403.15,79
PWM_HIB: J1.9 R13.1 | length 2559.8
  Top Layer w20: J1.9@3203.15,79 3273.15,149 5450,149 5564.61,263.61 R13.1@5564.61,385.51
PWM_LI_AF: C2.1 R9.2 U1.6 | length 196.7
  Top Layer w20: U1.6@278.15,566.36 278.15,505.85 288.15,495.85 C2.1@288.15,443.84 R9.2@358.15,443.84
PWM_LI_BF: C5.1 R14.2 U4.6 | length 191.5
  Top Layer w20: U4.6@5695,566.02 5695,508.51 5704.61,498.9 C5.1@5704.61,448.5 R14.2@5774.61,448.5
PWM_LIA: J1.2 R9.1 | length 2299.3
  Top Layer w20: R9.1@358.15,380.85 358.15,330.85 555,134 2448.15,134 J1.2@2503.15,79
PWM_LIB: J1.10 R14.1 | length 2669.2
  Top Layer w20: J1.10@3303.15,79 3353.15,79 3383.15,109 5619,109 5774.61,264.61 R14.1@5774.61,385.51
TEMP_SENSE1: C19.1 J1.8 R43.2 | length 1788.4
  Top Layer w15: R43.2@3443.5,1485 C19.1@3443.5,1415.78 3443.5,1376.5 3480,1340 v1(3535,1340)
  Bottom Layer w15: J1.8@3103.15,79 3148.15,124 3148.15,1025.85 3188.15,1065.85 3415.85,1065.85 3475,1125 3475,1280 v1(3535,1340)
V+: C7.1 C13.1 C14.1 D17.2 R29.2 U2.2 U4.1 | length 6328.5
  Top Layer w20: v1(2598.5,1758.5) C7.1@2598.5,1705 2598.5,1676.5 2626.65,1648.35 U2.2@2626.65,1513.79 ; v1(3028.15,242.74) 3208.08,242.74 3256.82,194 5439,194 5490,245 v1(5490,295) ; R29.2@5767.09,1115.26 5767.09,1031.85 C13.1@5818.43,980.51 5945,980.51 5975,950.51 5975,778.58 5955,758.58 C14.1@5905.36,758.58 C14.1@5901.78,755 ; U4.1@5795,755 C14.1@5901.78,755 ; v1(5975,690.51) 5974.88,690.63 D17.2@5905,690.63 5901.78,693.85 C14.1@5901.78,755
  Bottom Layer w20: v1(2598.5,1758.5) 2598.5,1540.5 2675,1464 2675,1190.85 2750,1115.85 2918.15,1115.85 2968.15,1065.85 2968.15,420.94 2927.15,379.94 2927.15,281.22 2965.63,242.74 v1(3028.15,242.74) ; v1(5490,295) 5895,295 5975,375 v1(5975,690.51)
